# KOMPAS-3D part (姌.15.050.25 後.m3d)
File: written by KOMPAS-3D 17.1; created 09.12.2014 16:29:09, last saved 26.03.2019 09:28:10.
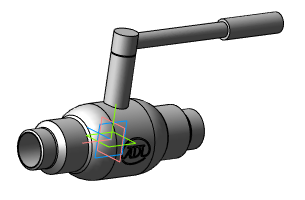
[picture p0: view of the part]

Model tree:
1. Операция без истории:4  (labels: Сталь 20  ГОСТ 1050-88)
